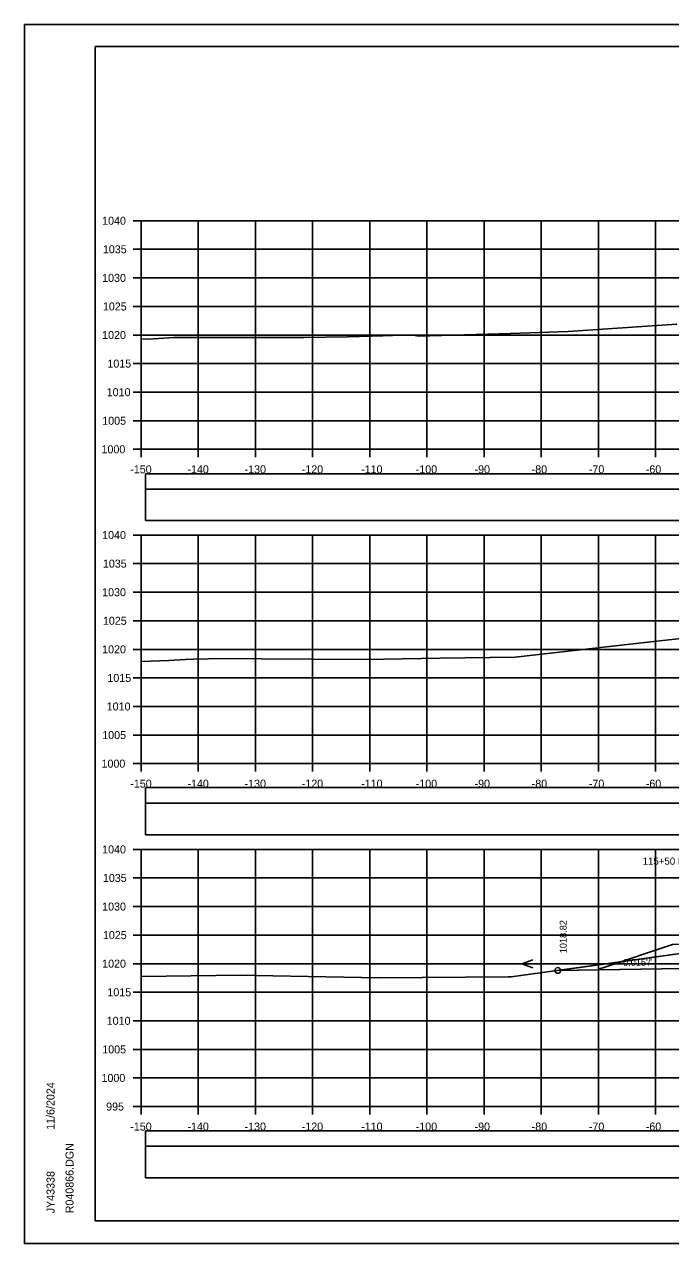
# Model space of a CAD drawing. Extents: x 1370565 to 1374448, y 301010 to 304637.
# Drawn here: x 1370564.6 to 1370677.7, y 302717.2 to 302930.5 of the extents above; entities that cross this region are included whole.
import ezdxf

# ---------------------------------------------------------------- set-up
doc = ezdxf.new("R2010")
doc.units = 0
for name, color, linetype in [('Default', 7, 'Continuous'), ('R_Axis', 7, 'Continuous'), ('R_Axis Annot', 7, 'Continuous'), ('R_Border', 7, 'Continuous'), ('R_Contours', 7, 'Continuous'), ('R_Drive', 7, 'Continuous'), ('R_Exist Surface', 7, 'Continuous'), ('R_Fin Surface', 7, 'Continuous'), ('R_Grid', 7, 'Continuous'), ('R_No Plot', 7, 'Continuous'), ('R_Water Annot', 7, 'Continuous'), ('R_Xsect Elev', 7, 'Continuous'), ('R_Xsect Slope', 7, 'Continuous')]:
    doc.layers.add(name, color=color, linetype=linetype)

msp = doc.modelspace()

# ---------------------------------------------------------------- linework, layer by layer
at = {"layer": 'Default'}
for points in [[(1370585.82, 302788.75), (1370884.24, 302788.75), (1370884.24, 302794.27), (1370585.82, 302794.27)], [(1370585.82, 302728.7), (1370884.24, 302728.7), (1370884.24, 302734.22), (1370585.82, 302734.22)]]:
    msp.add_lwpolyline(points, close=True, dxfattribs=at)
at = {"layer": 'R_Axis'}
for p, q in [((1370583.63, 302896.18), (1370585.03, 302896.18)), ((1370585.03, 302856.18), (1370585.03, 302896.18)), ((1370583.63, 302891.18), (1370585.03, 302891.18)), ((1370583.63, 302886.18), (1370585.03, 302886.18)), ((1370583.63, 302881.18), (1370585.03, 302881.18)), ((1370583.63, 302876.18), (1370585.03, 302876.18)), ((1370583.63, 302871.18), (1370585.03, 302871.18)), ((1370583.63, 302866.18), (1370585.03, 302866.18)), ((1370583.63, 302861.18), (1370585.03, 302861.18)), ((1370583.63, 302856.18), (1370585.03, 302856.18)), ((1370585.03, 302856.18), (1370885.03, 302856.18)), ((1370585.03, 302854.78), (1370585.03, 302856.18)), ((1370595.03, 302854.78), (1370595.03, 302856.18)), ((1370605.03, 302854.78), (1370605.03, 302856.18)), ((1370615.03, 302854.78), (1370615.03, 302856.18)), ((1370625.03, 302854.78), (1370625.03, 302856.18)), ((1370635.03, 302854.78), (1370635.03, 302856.18)), ((1370645.03, 302854.78), (1370645.03, 302856.18)), ((1370655.03, 302854.78), (1370655.03, 302856.18)), ((1370665.03, 302854.78), (1370665.03, 302856.18)), ((1370675.03, 302854.78), (1370675.03, 302856.18)), ((1370583.63, 302841.18), (1370585.03, 302841.18)), ((1370585.03, 302801.18), (1370585.03, 302841.18)), ((1370583.63, 302836.18), (1370585.03, 302836.18)), ((1370583.63, 302831.18), (1370585.03, 302831.18)), ((1370583.63, 302826.18), (1370585.03, 302826.18)), ((1370583.63, 302821.18), (1370585.03, 302821.18)), ((1370583.63, 302816.18), (1370585.03, 302816.18)), ((1370583.63, 302811.18), (1370585.03, 302811.18)), ((1370583.63, 302806.18), (1370585.03, 302806.18)), ((1370583.63, 302801.18), (1370585.03, 302801.18)), ((1370585.03, 302801.18), (1370885.03, 302801.18)), ((1370585.03, 302799.78), (1370585.03, 302801.18)), ((1370595.03, 302799.78), (1370595.03, 302801.18)), ((1370605.03, 302799.78), (1370605.03, 302801.18)), ((1370615.03, 302799.78), (1370615.03, 302801.18)), ((1370625.03, 302799.78), (1370625.03, 302801.18)), ((1370635.03, 302799.78), (1370635.03, 302801.18)), ((1370645.03, 302799.78), (1370645.03, 302801.18)), ((1370655.03, 302799.78), (1370655.03, 302801.18)), ((1370665.03, 302799.78), (1370665.03, 302801.18)), ((1370675.03, 302799.78), (1370675.03, 302801.18)), ((1370583.63, 302786.18), (1370585.03, 302786.18)), ((1370585.03, 302741.18), (1370585.03, 302786.18)), ((1370583.63, 302781.18), (1370585.03, 302781.18)), ((1370583.63, 302776.18), (1370585.03, 302776.18)), ((1370583.63, 302771.18), (1370585.03, 302771.18)), ((1370583.63, 302766.18), (1370585.03, 302766.18)), ((1370583.63, 302761.18), (1370585.03, 302761.18)), ((1370583.63, 302756.18), (1370585.03, 302756.18)), ((1370583.63, 302751.18), (1370585.03, 302751.18)), ((1370583.63, 302746.18), (1370585.03, 302746.18)), ((1370583.63, 302741.18), (1370585.03, 302741.18)), ((1370585.03, 302741.18), (1370885.03, 302741.18)), ((1370585.03, 302739.78), (1370585.03, 302741.18)), ((1370595.03, 302739.78), (1370595.03, 302741.18)), ((1370605.03, 302739.78), (1370605.03, 302741.18)), ((1370615.03, 302739.78), (1370615.03, 302741.18)), ((1370625.03, 302739.78), (1370625.03, 302741.18)), ((1370635.03, 302739.78), (1370635.03, 302741.18)), ((1370645.03, 302739.78), (1370645.03, 302741.18)), ((1370655.03, 302739.78), (1370655.03, 302741.18)), ((1370665.03, 302739.78), (1370665.03, 302741.18)), ((1370675.03, 302739.78), (1370675.03, 302741.18))]:
    msp.add_line(p, q, dxfattribs=at)
at = {"layer": 'R_Border'}
for p, q in [((1370577.03, 302926.64), (1370893.21, 302926.64)), ((1370577.03, 302721.18), (1370577.03, 302926.64)), ((1370577.03, 302721.18), (1370577.03, 302721.18)), ((1370893.21, 302721.18), (1370577.03, 302721.18))]:
    msp.add_line(p, q, dxfattribs=at)
at = {"layer": 'R_Contours'}
for p, q in [((1370669.01, 302766.52), (1370657.93, 302765)), ((1370657.93, 302765), (1370665.04, 302765.11)), ((1370666.19, 302765.58), (1370665.04, 302765.2)), ((1370669.01, 302766.52), (1370666.19, 302765.58))]:
    msp.add_line(p, q, dxfattribs=at)
for points in [[(1370665.04, 302765.11), (1370687.16, 302765.44), (1370695.74, 302768.3)], [(1370695.74, 302768.3), (1370692.06, 302768.34), (1370691.35, 302768.34), (1370681.39, 302768.17), (1370680.94, 302768.16), (1370679.32, 302767.95), (1370669.01, 302766.52)], [(1370665.04, 302765.2), (1370666.19, 302765.58), (1370669.01, 302766.52)], [(1370665.04, 302765.11), (1370665.04, 302765.2)], [(1370665.04, 302765.2), (1370665.04, 302765.11)]]:
    msp.add_lwpolyline(points, dxfattribs=at)
at = {"layer": 'R_Drive'}
for points in [[(1370585.82, 302849.22), (1370884.24, 302849.22), (1370884.24, 302851.92), (1370585.82, 302851.92)], [(1370585.82, 302843.7), (1370884.24, 302843.7), (1370884.24, 302849.22), (1370585.82, 302849.22)], [(1370585.82, 302794.27), (1370884.24, 302794.27), (1370884.24, 302796.98), (1370585.82, 302796.98)], [(1370585.82, 302734.22), (1370884.24, 302734.22), (1370884.24, 302736.92), (1370585.82, 302736.92)]]:
    msp.add_lwpolyline(points, close=True, dxfattribs=at)
msp.add_lwpolyline([(1370665.04, 302765.2), (1370666.19, 302765.58), (1370678.03, 302769.53), (1370685.32, 302769.68), (1370686.03, 302769.69), (1370693.32, 302769.84), (1370694.03, 302769.85), (1370699.9, 302769.97), (1370700.51, 302769.98)], dxfattribs=at)
at = {"layer": 'R_Exist Surface'}
for points in [[(1370585.03, 302875.5), (1370586.34, 302875.48), (1370590.75, 302875.72), (1370593.66, 302875.75), (1370599.3, 302875.74), (1370603.15, 302875.72), (1370612.98, 302875.75), (1370613.17, 302875.75), (1370613.53, 302875.76), (1370621.13, 302875.88), (1370627.34, 302876.05), (1370632.41, 302876.19), (1370632.69, 302876.14), (1370633.58, 302875.97), (1370649.64, 302876.47), (1370659.74, 302876.82), (1370678.76, 302878.08)], [(1370585.03, 302819.06), (1370589.89, 302819.21), (1370592.75, 302819.38), (1370594.21, 302819.46), (1370599.32, 302819.59), (1370606.08, 302819.53), (1370624.24, 302819.38), (1370637.33, 302819.61), (1370650.48, 302819.81), (1370673.69, 302822.45), (1370682.14, 302823.37)], [(1370585.03, 302763.95), (1370602.46, 302764.15), (1370608.1, 302764.07), (1370626.66, 302763.72), (1370649.27, 302763.87), (1370649.78, 302763.88), (1370655.24, 302764.63), (1370679.32, 302767.95)]]:
    msp.add_lwpolyline(points, dxfattribs=at)
at = {"layer": 'R_Fin Surface'}
msp.add_lwpolyline([(1370657.93, 302765), (1370687.16, 302765.44), (1370706.03, 302771.72), (1370714.53, 302773.14), (1370724.03, 302773.57), (1370735.03, 302774.06), (1370746.03, 302774.55), (1370750.03, 302774.73), (1370764.03, 302772.4), (1370813.59, 302755.88), (1370825.59, 302755.88), (1370848.25, 302763.43)], dxfattribs=at)
at = {"layer": 'R_Grid'}
for p, q in [((1370585.03, 302896.18), (1370885.03, 302896.18)), ((1370585.03, 302856.18), (1370585.03, 302896.18)), ((1370595.03, 302856.18), (1370595.03, 302896.18)), ((1370605.03, 302856.18), (1370605.03, 302896.18)), ((1370615.03, 302856.18), (1370615.03, 302896.18)), ((1370625.03, 302856.18), (1370625.03, 302896.18)), ((1370635.03, 302856.18), (1370635.03, 302896.18)), ((1370645.03, 302856.18), (1370645.03, 302896.18)), ((1370655.03, 302856.18), (1370655.03, 302896.18)), ((1370665.03, 302856.18), (1370665.03, 302896.18)), ((1370675.03, 302856.18), (1370675.03, 302896.18)), ((1370585.03, 302891.18), (1370885.03, 302891.18)), ((1370585.03, 302886.18), (1370885.03, 302886.18)), ((1370585.03, 302881.18), (1370885.03, 302881.18)), ((1370585.03, 302876.18), (1370885.03, 302876.18)), ((1370585.03, 302871.18), (1370885.03, 302871.18)), ((1370585.03, 302866.18), (1370885.03, 302866.18)), ((1370585.03, 302861.18), (1370885.03, 302861.18)), ((1370585.03, 302856.18), (1370885.03, 302856.18)), ((1370585.03, 302841.18), (1370885.03, 302841.18)), ((1370585.03, 302801.18), (1370585.03, 302841.18)), ((1370595.03, 302801.18), (1370595.03, 302841.18)), ((1370605.03, 302801.18), (1370605.03, 302841.18)), ((1370615.03, 302801.18), (1370615.03, 302841.18)), ((1370625.03, 302801.18), (1370625.03, 302841.18)), ((1370635.03, 302801.18), (1370635.03, 302841.18)), ((1370645.03, 302801.18), (1370645.03, 302841.18)), ((1370655.03, 302801.18), (1370655.03, 302841.18)), ((1370665.03, 302801.18), (1370665.03, 302841.18)), ((1370675.03, 302801.18), (1370675.03, 302841.18)), ((1370585.03, 302836.18), (1370885.03, 302836.18)), ((1370585.03, 302831.18), (1370885.03, 302831.18)), ((1370585.03, 302826.18), (1370885.03, 302826.18)), ((1370585.03, 302821.18), (1370885.03, 302821.18)), ((1370585.03, 302816.18), (1370885.03, 302816.18)), ((1370585.03, 302811.18), (1370885.03, 302811.18)), ((1370585.03, 302806.18), (1370885.03, 302806.18)), ((1370585.03, 302801.18), (1370885.03, 302801.18)), ((1370585.03, 302786.18), (1370885.03, 302786.18)), ((1370585.03, 302741.18), (1370585.03, 302786.18)), ((1370595.03, 302741.18), (1370595.03, 302786.18)), ((1370605.03, 302741.18), (1370605.03, 302786.18)), ((1370615.03, 302741.18), (1370615.03, 302786.18)), ((1370625.03, 302741.18), (1370625.03, 302786.18)), ((1370635.03, 302741.18), (1370635.03, 302786.18)), ((1370645.03, 302741.18), (1370645.03, 302786.18)), ((1370655.03, 302741.18), (1370655.03, 302786.18)), ((1370665.03, 302741.18), (1370665.03, 302786.18)), ((1370675.03, 302741.18), (1370675.03, 302786.18)), ((1370585.03, 302781.18), (1370885.03, 302781.18)), ((1370585.03, 302776.18), (1370885.03, 302776.18)), ((1370585.03, 302771.18), (1370885.03, 302771.18)), ((1370585.03, 302766.18), (1370885.03, 302766.18)), ((1370585.03, 302761.18), (1370885.03, 302761.18)), ((1370585.03, 302756.18), (1370885.03, 302756.18)), ((1370585.03, 302751.18), (1370885.03, 302751.18)), ((1370585.03, 302746.18), (1370885.03, 302746.18)), ((1370585.03, 302741.18), (1370885.03, 302741.18))]:
    msp.add_line(p, q, dxfattribs=at)
at = {"layer": 'R_No Plot'}
for p, q in [((1370564.63, 302930.53), (1370897.96, 302930.53)), ((1370564.63, 302717.2), (1370897.96, 302717.2))]:
    msp.add_line(p, q, dxfattribs=at)
for points in [[(1370564.62, 302930.53), (1370897.96, 302930.53), (1370897.96, 302717.2), (1370564.62, 302717.2)], [(1370810.95, 302926.64), (1370830.57, 302926.64), (1370830.57, 302916.76), (1370846.68, 302916.76), (1370869.88, 302916.76), (1370869.88, 302884.09), (1370893.09, 302884.09), (1370893.21, 302721.18), (1370577.03, 302721.18), (1370577.03, 302926.64)]]:
    msp.add_lwpolyline(points, close=True, dxfattribs=at)
msp.add_circle((1370657.93, 302765), 0.5, dxfattribs=at)
at = {"layer": 'R_Water Annot'}
for p, q in [((1370651.64, 302766.13), (1370653.57, 302766.83)), ((1370657.93, 302766.13), (1370651.64, 302766.13)), ((1370651.64, 302766.13), (1370653.57, 302765.43))]:
    msp.add_line(p, q, dxfattribs=at)

# ---------------------------------------------------------------- texts
at = {"layer": 'R_Axis Annot'}
for s, p in [('1040', (1370578.22, 302895.48)), ('1035', (1370578.35, 302890.48)), ('1030', (1370578.22, 302885.48)), ('1025', (1370578.35, 302880.48)), ('1020', (1370578.22, 302875.48)), ('1015', (1370579.14, 302870.48)), ('1010', (1370579.02, 302865.48)), ('1005', (1370578.24, 302860.48)), ('1000', (1370578.11, 302855.48)), ('-150', (1370583.14, 302851.98)), ('-140', (1370593.14, 302851.98)), ('-130', (1370603.14, 302851.98)), ('-120', (1370613.14, 302851.98)), ('-110', (1370623.53, 302851.98)), ('-100', (1370633.08, 302851.98)), ('-90', (1370643.37, 302851.98)), ('-80', (1370653.37, 302851.98)), ('-70', (1370663.37, 302851.98)), ('-60', (1370673.33, 302851.98)), ('1040', (1370578.22, 302840.48)), ('1035', (1370578.35, 302835.48)), ('1030', (1370578.22, 302830.48)), ('1025', (1370578.35, 302825.48)), ('1020', (1370578.22, 302820.48)), ('1015', (1370579.14, 302815.48)), ('1010', (1370579.02, 302810.48)), ('1005', (1370578.24, 302805.48)), ('1000', (1370578.11, 302800.48)), ('-150', (1370583.14, 302796.98)), ('-140', (1370593.14, 302796.98)), ('-130', (1370603.14, 302796.98)), ('-120', (1370613.14, 302796.98)), ('-110', (1370623.53, 302796.98)), ('-100', (1370633.08, 302796.98)), ('-90', (1370643.37, 302796.98)), ('-80', (1370653.37, 302796.98)), ('-70', (1370663.37, 302796.98)), ('-60', (1370673.33, 302796.98)), ('1040', (1370578.22, 302785.48)), ('1035', (1370578.35, 302780.48)), ('1030', (1370578.22, 302775.48)), ('1025', (1370578.35, 302770.48)), ('1020', (1370578.22, 302765.48)), ('1015', (1370579.14, 302760.48)), ('1010', (1370579.02, 302755.48)), ('1005', (1370578.24, 302750.48)), ('1000', (1370578.11, 302745.48)), ('995', (1370578.92, 302740.48)), ('-150', (1370583.14, 302736.98)), ('-140', (1370593.14, 302736.98)), ('-130', (1370603.14, 302736.98)), ('-120', (1370613.14, 302736.98)), ('-110', (1370623.53, 302736.98)), ('-100', (1370633.08, 302736.98)), ('-90', (1370643.37, 302736.98)), ('-80', (1370653.37, 302736.98)), ('-70', (1370663.37, 302736.98)), ('-60', (1370673.33, 302736.98))]:
    msp.add_text(s, height=1.4, dxfattribs=at).set_placement(p)
at = {"layer": 'R_Border'}
for s, p in [('11/6/2024', (1370569.89, 302737.11)), ('R040866.DGN', (1370573.22, 302722.5)), ('JY43338', (1370569.89, 302722.5))]:
    msp.add_text(s, height=1.4, rotation=90, dxfattribs=at).set_placement(p)
at = {"layer": 'R_Water Annot'}
msp.add_text('115+50 DRIVEWAY', height=1.2661, dxfattribs=at).set_placement((1370672.78, 302783.49))
at = {"layer": 'R_Xsect Elev'}
msp.add_text('1018.82', height=1.2, rotation=90, dxfattribs=at).set_placement((1370659.48, 302768))
at = {"layer": 'R_Xsect Slope'}
msp.add_text("0.015'/'", height=1.2, rotation=0.8594, dxfattribs=at).set_placement((1370669.36, 302765.77))

doc.saveas('drawing.dxf')
